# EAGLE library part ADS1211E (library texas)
24-Bit ANALOG-TO-DIGITAL CONVERTER Source: http://focus.ti.com/lit/ds/symlink/ads1210.pdf
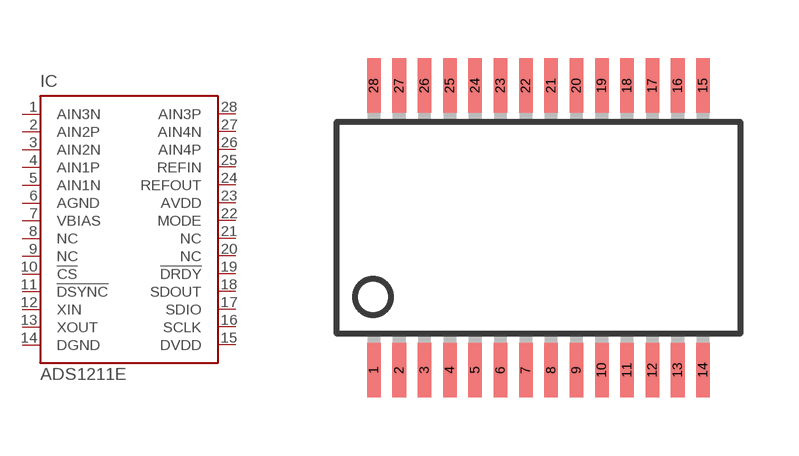
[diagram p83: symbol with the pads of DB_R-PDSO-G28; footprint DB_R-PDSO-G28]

Designator prefix IC

## ADS1211E (MF: TEXAS INSTRUMENT CONNECTORS; MPN: ADS1211E; OC_FARNELL: unknown; OC_NEWARK: 74C6976)  [DB_R-PDSO-G28]
1  AIN3N  in
2  AIN2P  in
3  AIN2N  in
4  AIN1P  in
5  AIN1N  in
6  AGND  pwr
7  VBIAS  in
8  NC  nc
9  NC  nc
10  !CS  in
11  !DSYNC  in
12  XIN  in
13  XOUT  out
14  DGND  pwr
15  DVDD  pwr
16  SCLK
17  SDIO
18  SDOUT  out
19  !DRDY  out
20  NC  nc
21  NC  nc
22  MODE  in
23  AVDD  pwr
24  REFOUT  out
25  REFIN  in
26  AIN4P  in
27  AIN4N  in
28  AIN3P  in

## Footprint DB_R-PDSO-G28 (pad centres in mm)
DB (R-PDSO-G28) Source: http://focus.ti.com/lit/ds/symlink/ads1210.pdf
smd 0.348 x 1.397: 1 -4.225,-3.656; 2 -3.575,-3.656; 3 -2.925,-3.656; 4 -2.275,-3.656; 5 -1.625,-3.656; 6 -0.975,-3.656; 7 -0.325,-3.656; 8 0.325,-3.656; 9 0.975,-3.656; 10 1.625,-3.656; 11 2.275,-3.656; 12 2.925,-3.656; 13 3.575,-3.656; 14 4.225,-3.656; 15 4.225,3.656; 16 3.575,3.656; 17 2.925,3.656; 18 2.275,3.656; 19 1.625,3.656; 20 0.975,3.656; 21 0.325,3.656; 22 -0.325,3.656; 23 -0.975,3.656; 24 -1.625,3.656; 25 -2.275,3.656; 26 -2.925,3.656; 27 -3.575,3.656; 28 -4.225,3.656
